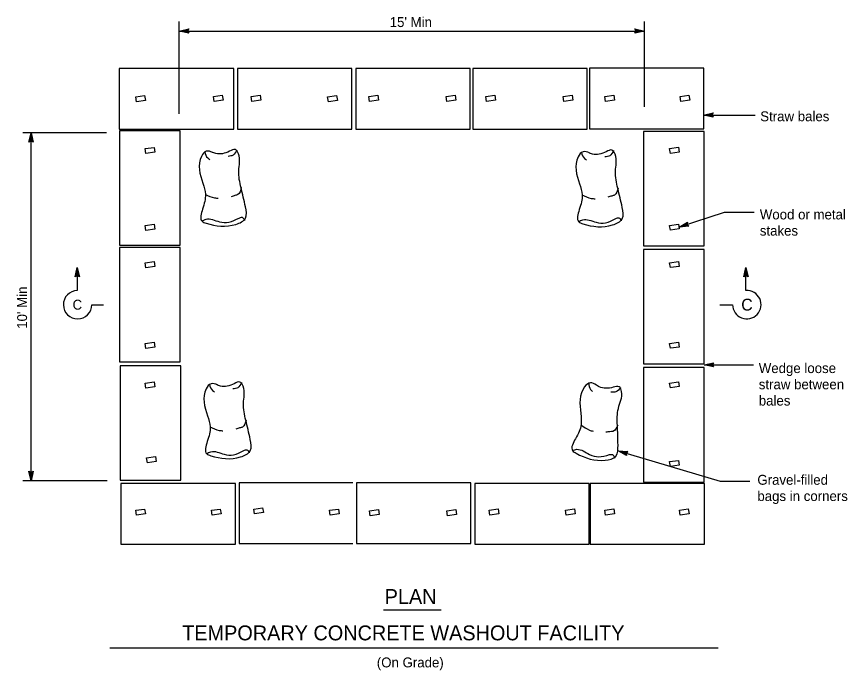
# Model space of a CAD drawing. Extents: x 6708826 to 6711089, y 1868571 to 1869537.
# Drawn here: x 6709434 to 6709938, y 1868641 to 1869038 of the extents above; entities that cross this region are included whole.
import ezdxf

# ---------------------------------------------------------------- set-up
doc = ezdxf.new("R2010")
doc.units = 0
for name, color, linetype in [('1 Control', 7, 'Continuous'), ('56 Stg 3 Anno', 7, 'Continuous'), ('57 Undefined', 7, 'Continuous'), ('60 Nongeo Data', 7, 'Continuous')]:
    doc.layers.add(name, color=color, linetype=linetype)

msp = doc.modelspace()

# ---------------------------------------------------------------- linework, layer by layer
at = {"layer": '1 Control'}
for p, q in [((6709798.85, 1868774.43), (6709798.85, 1868774.43)), ((6709804, 1868771.55), (6709804, 1868771.55)), ((6709804.73, 1868774.01), (6709804.73, 1868774.01))]:
    msp.add_line(p, q, dxfattribs=at)
msp.add_lwpolyline([(6709804, 1868771.55), (6709798.85, 1868774.43), (6709804.73, 1868774.01), (6709804.44, 1868773.74), (6709800.13, 1868774.05), (6709803.9, 1868771.94), (6709803.81, 1868772.32), (6709801.39, 1868773.67), (6709804.15, 1868773.48), (6709803.85, 1868773.21), (6709802.66, 1868773.29), (6709803.71, 1868772.71), (6709803.63, 1868773.01), (6709804.73, 1868774.01), (6709803.63, 1868773.01)], close=True, dxfattribs=at)
at = {"layer": '56 Stg 3 Anno'}
for p, q in [((6709532.76, 1868978.54), (6709532.76, 1869034.49)), ((6709814.79, 1868982.86), (6709814.79, 1869034.49)), ((6709532.76, 1869028.82), (6709538.52, 1869030.09)), ((6709532.76, 1869028.82), (6709538.52, 1869030.09)), ((6709532.76, 1869028.82), (6709814.79, 1869028.82)), ((6709538.52, 1869027.53), (6709532.76, 1869028.82)), ((6709532.76, 1869028.82), (6709532.76, 1869028.82)), ((6709538.52, 1869027.53), (6709532.76, 1869028.82)), ((6709532.76, 1869028.82), (6709532.76, 1869028.82)), ((6709538.32, 1869027.87), (6709534.09, 1869028.81)), ((6709538.32, 1869027.87), (6709534.09, 1869028.81)), ((6709534.1, 1869028.82), (6709538.3, 1869029.75)), ((6709534.1, 1869028.82), (6709538.3, 1869029.75)), ((6709535.42, 1869028.81), (6709538.13, 1869029.41)), ((6709535.42, 1869028.81), (6709538.13, 1869029.41)), ((6709538.09, 1869028.22), (6709535.42, 1869028.81)), ((6709538.09, 1869028.22), (6709535.42, 1869028.81)), ((6709536.74, 1869028.81), (6709537.9, 1869029.07)), ((6709536.74, 1869028.81), (6709537.9, 1869029.07)), ((6709537.92, 1869028.55), (6709536.74, 1869028.81)), ((6709537.92, 1869028.55), (6709536.74, 1869028.81)), ((6709538.52, 1869030.09), (6709537.76, 1869028.82)), ((6709538.52, 1869030.09), (6709537.76, 1869028.82)), ((6709537.76, 1869028.82), (6709538.52, 1869027.53)), ((6709537.76, 1869028.82), (6709538.52, 1869027.53)), ((6709538.52, 1869030.09), (6709538.52, 1869030.09)), ((6709538.52, 1869030.09), (6709538.52, 1869030.09)), ((6709538.52, 1869027.53), (6709538.52, 1869027.53)), ((6709538.52, 1869027.53), (6709538.52, 1869027.53)), ((6709809.8, 1869028.82), (6709809.03, 1869030.1)), ((6709809.03, 1869030.1), (6709809.03, 1869030.1)), ((6709809.03, 1869030.1), (6709814.79, 1869028.82)), ((6709814.79, 1869028.82), (6709809.03, 1869027.54)), ((6709809.03, 1869027.54), (6709809.8, 1869028.82)), ((6709809.03, 1869027.54), (6709809.03, 1869027.54)), ((6709809.24, 1869029.76), (6709813.47, 1869028.82)), ((6709813.46, 1869028.81), (6709809.26, 1869027.88)), ((6709812.14, 1869028.82), (6709809.43, 1869028.22)), ((6709809.47, 1869029.41), (6709812.14, 1869028.82)), ((6709809.64, 1869029.08), (6709810.82, 1869028.82)), ((6709810.82, 1869028.82), (6709809.66, 1869028.56)), ((6709814.79, 1869028.82), (6709814.79, 1869028.82)), ((6709850.7, 1868977.91), (6709856.46, 1868979.18)), ((6709850.7, 1868977.91), (6709881.9, 1868977.91)), ((6709856.46, 1868976.62), (6709850.7, 1868977.91)), ((6709850.7, 1868977.91), (6709850.7, 1868977.91)), ((6709856.25, 1868976.96), (6709852.03, 1868977.91)), ((6709852.04, 1868977.91), (6709856.24, 1868978.84)), ((6709853.35, 1868977.91), (6709856.07, 1868978.51)), ((6709856.03, 1868977.31), (6709853.35, 1868977.91)), ((6709854.68, 1868977.9), (6709855.84, 1868978.16)), ((6709855.86, 1868977.64), (6709854.68, 1868977.9)), ((6709856.46, 1868979.18), (6709855.69, 1868977.91)), ((6709855.69, 1868977.91), (6709856.46, 1868976.62)), ((6709856.46, 1868979.18), (6709856.46, 1868979.18)), ((6709856.46, 1868976.62), (6709856.46, 1868976.62)), ((6709488.73, 1868967.19), (6709437.9, 1868967.19)), ((6709441.64, 1868961.43), (6709442.93, 1868967.19)), ((6709442.93, 1868756.37), (6709442.93, 1868967.19)), ((6709442.93, 1868967.19), (6709442.93, 1868967.19)), ((6709442.93, 1868967.19), (6709444.2, 1868961.43)), ((6709442.93, 1868962.19), (6709441.64, 1868961.43)), ((6709441.64, 1868961.43), (6709441.64, 1868961.43)), ((6709441.98, 1868961.63), (6709442.93, 1868965.86)), ((6709442.33, 1868961.86), (6709442.93, 1868964.53)), ((6709442.66, 1868962.03), (6709442.92, 1868963.21)), ((6709442.92, 1868963.21), (6709443.18, 1868962.05)), ((6709442.93, 1868965.85), (6709443.86, 1868961.65)), ((6709442.93, 1868964.53), (6709443.53, 1868961.82)), ((6709444.2, 1868961.43), (6709442.93, 1868962.19)), ((6709444.2, 1868961.43), (6709444.2, 1868961.43)), ((6709863.16, 1868918.83), (6709835.83, 1868909.95)), ((6709881.39, 1868918.83), (6709863.16, 1868918.83)), ((6709835.83, 1868909.95), (6709840.91, 1868912.94)), ((6709837.1, 1868910.36), (6709840.8, 1868912.54)), ((6709838.35, 1868910.76), (6709840.74, 1868912.17)), ((6709841.08, 1868911.02), (6709838.35, 1868910.76)), ((6709839.61, 1868911.17), (6709840.64, 1868911.78)), ((6709840.82, 1868911.29), (6709839.61, 1868911.17)), ((6709840.91, 1868912.94), (6709840.58, 1868911.49)), ((6709840.58, 1868911.49), (6709841.7, 1868910.5)), ((6709840.91, 1868912.94), (6709840.91, 1868912.94)), ((6709841.7, 1868910.5), (6709835.83, 1868909.95)), ((6709835.83, 1868909.95), (6709835.83, 1868909.95)), ((6709841.4, 1868910.76), (6709837.09, 1868910.36)), ((6709841.7, 1868910.5), (6709841.7, 1868910.5)), ((6709469.7, 1868879.8), (6709470.99, 1868885.56)), ((6709470.05, 1868880.01), (6709470.99, 1868884.24)), ((6709470.39, 1868880.23), (6709470.99, 1868882.91)), ((6709470.73, 1868880.4), (6709470.99, 1868881.58)), ((6709470.99, 1868885.56), (6709470.99, 1868885.56)), ((6709470.99, 1868885.56), (6709472.27, 1868879.8)), ((6709470.99, 1868885.56), (6709470.99, 1868871.63)), ((6709470.99, 1868884.23), (6709471.92, 1868880.02)), ((6709470.99, 1868882.91), (6709471.59, 1868880.19)), ((6709470.99, 1868881.58), (6709471.25, 1868880.42)), ((6709875.11, 1868879.8), (6709876.4, 1868885.56)), ((6709875.45, 1868880), (6709876.4, 1868884.23)), ((6709875.8, 1868880.23), (6709876.4, 1868882.91)), ((6709876.13, 1868880.4), (6709876.4, 1868881.58)), ((6709876.4, 1868885.56), (6709876.4, 1868885.56)), ((6709876.4, 1868885.56), (6709877.68, 1868879.8)), ((6709876.4, 1868871.63), (6709876.4, 1868885.56)), ((6709876.4, 1868884.22), (6709877.33, 1868880.02)), ((6709876.4, 1868882.91), (6709877, 1868880.19)), ((6709876.4, 1868881.58), (6709876.65, 1868880.42)), ((6709470.99, 1868880.57), (6709469.7, 1868879.8)), ((6709469.7, 1868879.8), (6709469.7, 1868879.8)), ((6709472.27, 1868879.8), (6709470.99, 1868880.57)), ((6709472.27, 1868879.8), (6709472.27, 1868879.8)), ((6709876.4, 1868880.56), (6709875.11, 1868879.8)), ((6709875.11, 1868879.8), (6709875.11, 1868879.8)), ((6709877.68, 1868879.8), (6709876.4, 1868880.56)), ((6709877.68, 1868879.8), (6709877.68, 1868879.8)), ((6709479.79, 1868863), (6709486.92, 1868863)), ((6709860.6, 1868863), (6709868.33, 1868863)), ((6709851, 1868826.55), (6709856.76, 1868827.82)), ((6709851, 1868826.55), (6709880.87, 1868826.55)), ((6709856.76, 1868825.26), (6709851, 1868826.55)), ((6709851, 1868826.55), (6709851, 1868826.55)), ((6709856.55, 1868825.6), (6709852.33, 1868826.55)), ((6709852.34, 1868826.55), (6709856.54, 1868827.48)), ((6709853.65, 1868826.54), (6709856.37, 1868827.15)), ((6709856.33, 1868825.95), (6709853.65, 1868826.54)), ((6709854.98, 1868826.54), (6709856.14, 1868826.8)), ((6709856.16, 1868826.28), (6709854.98, 1868826.54)), ((6709856.76, 1868827.82), (6709855.99, 1868826.55)), ((6709855.99, 1868826.55), (6709856.76, 1868825.26)), ((6709856.76, 1868827.82), (6709856.76, 1868827.82)), ((6709856.76, 1868825.26), (6709856.76, 1868825.26)), ((6709798.85, 1868774.43), (6709860.68, 1868756.04)), ((6709442.93, 1868756.37), (6709441.65, 1868762.14)), ((6709441.65, 1868762.14), (6709441.65, 1868762.14)), ((6709441.65, 1868762.14), (6709442.93, 1868761.37)), ((6709442.92, 1868757.71), (6709442, 1868761.91)), ((6709442.93, 1868759.03), (6709442.33, 1868761.74)), ((6709442.93, 1868760.35), (6709442.67, 1868761.51)), ((6709442.93, 1868761.37), (6709444.21, 1868762.14)), ((6709444.21, 1868762.14), (6709442.93, 1868756.37)), ((6709443.87, 1868761.93), (6709442.93, 1868757.7)), ((6709443.53, 1868761.7), (6709442.93, 1868759.03)), ((6709443.19, 1868761.53), (6709442.93, 1868760.35)), ((6709444.21, 1868762.14), (6709444.21, 1868762.14)), ((6709489.1, 1868756.37), (6709437.9, 1868756.37)), ((6709442.93, 1868756.37), (6709442.93, 1868756.37)), ((6709860.68, 1868756.04), (6709878.82, 1868756.04))]:
    msp.add_line(p, q, dxfattribs=at)
for centre, start, end in [((6709471.16, 1868863.01), 91.113, 359.9585), ((6709876.92, 1868863.01), 180.1055, 93.4975)]:
    msp.add_arc(centre, 8.62, start, end, dxfattribs=at)
at = {"layer": '57 Undefined'}
for p, q in [((6709656.61, 1868678.17), (6709691.63, 1868678.17)), ((6709490.67, 1868655.17), (6709859.6, 1868655.17))]:
    msp.add_line(p, q, dxfattribs=at)
at = {"layer": '60 Nongeo Data'}
for points in [[(6709496.47, 1868969.31), (6709565.82, 1868969.31), (6709565.82, 1869006.05), (6709496.47, 1869006.05)], [(6709568.1, 1868969.31), (6709637.45, 1868969.31), (6709637.45, 1869006.05), (6709568.1, 1869006.05)], [(6709639.88, 1868969.38), (6709709.24, 1868969.38), (6709709.24, 1869006.12), (6709639.88, 1869006.12)], [(6709710.76, 1868969.38), (6709780.11, 1868969.38), (6709780.11, 1869006.12), (6709710.76, 1869006.12)], [(6709781.56, 1868969.48), (6709850.91, 1868969.48), (6709850.91, 1869006.23), (6709781.56, 1869006.23)], [(6709506.39, 1868989.01), (6709511.83, 1868989.8), (6709512.26, 1868986.8), (6709506.83, 1868986.01)], [(6709553.5, 1868989.11), (6709558.93, 1868989.9), (6709559.37, 1868986.9), (6709553.94, 1868986.11)], [(6709576.44, 1868989.11), (6709581.87, 1868989.9), (6709582.31, 1868986.9), (6709576.87, 1868986.11)], [(6709622.79, 1868989.01), (6709628.22, 1868989.8), (6709628.66, 1868986.8), (6709623.23, 1868986.01)], [(6709647.74, 1868989.18), (6709653.17, 1868989.97), (6709653.6, 1868986.97), (6709648.17, 1868986.18)], [(6709694.65, 1868989.08), (6709700.08, 1868989.87), (6709700.51, 1868986.87), (6709695.08, 1868986.08)], [(6709718.61, 1868989.18), (6709724.04, 1868989.97), (6709724.48, 1868986.97), (6709719.05, 1868986.18)], [(6709765.52, 1868989.08), (6709770.95, 1868989.87), (6709771.39, 1868986.87), (6709765.95, 1868986.08)], [(6709790.84, 1868989.18), (6709796.27, 1868989.97), (6709796.71, 1868986.97), (6709791.27, 1868986.18)], [(6709836.41, 1868989.18), (6709841.84, 1868989.97), (6709842.27, 1868986.97), (6709836.84, 1868986.18)], [(6709533.27, 1868899), (6709533.27, 1868968.35), (6709496.52, 1868968.35), (6709496.52, 1868899)], [(6709851, 1868898.66), (6709851, 1868968.01), (6709814.26, 1868968.01), (6709814.26, 1868898.66)], [(6709512.19, 1868957.54), (6709517.62, 1868958.33), (6709518.06, 1868955.33), (6709512.63, 1868954.54)], [(6709830.11, 1868957.61), (6709835.55, 1868958.4), (6709835.98, 1868955.4), (6709830.55, 1868954.61)], [(6709512.19, 1868911.01), (6709517.62, 1868911.8), (6709518.06, 1868908.81), (6709512.63, 1868908.01)], [(6709830.11, 1868911.08), (6709835.55, 1868911.87), (6709835.98, 1868908.88), (6709830.55, 1868908.08)], [(6709533.27, 1868828.33), (6709533.27, 1868897.68), (6709496.52, 1868897.68), (6709496.52, 1868828.33)], [(6709851, 1868827.19), (6709851, 1868896.54), (6709814.26, 1868896.54), (6709814.26, 1868827.19)], [(6709512.19, 1868888.37), (6709517.62, 1868889.16), (6709518.06, 1868886.16), (6709512.63, 1868885.37)], [(6709830.11, 1868888.44), (6709835.55, 1868889.23), (6709835.98, 1868886.23), (6709830.55, 1868885.44)], [(6709830.11, 1868839.56), (6709835.55, 1868840.36), (6709835.98, 1868837.36), (6709830.55, 1868836.57)], [(6709512.19, 1868839.49), (6709517.62, 1868840.29), (6709518.06, 1868837.29), (6709512.63, 1868836.49)], [(6709533.67, 1868756.69), (6709533.67, 1868826.04), (6709496.93, 1868826.04), (6709496.93, 1868756.69)], [(6709851, 1868755.55), (6709851, 1868824.91), (6709814.26, 1868824.91), (6709814.26, 1868755.55)], [(6709512.19, 1868815.48), (6709517.62, 1868816.27), (6709518.06, 1868813.27), (6709512.63, 1868812.48)], [(6709830.11, 1868815.55), (6709835.55, 1868816.34), (6709835.98, 1868813.34), (6709830.55, 1868812.55)], [(6709513.04, 1868770.2), (6709518.47, 1868770.99), (6709518.9, 1868767.99), (6709513.47, 1868767.2)], [(6709830.11, 1868767.91), (6709835.55, 1868768.7), (6709835.98, 1868765.7), (6709830.55, 1868764.91)], [(6709640.26, 1868718.35), (6709709.61, 1868718.35), (6709709.61, 1868755.09), (6709640.26, 1868755.09)], [(6709711.97, 1868717.97), (6709781.32, 1868717.97), (6709781.32, 1868754.71), (6709711.97, 1868754.71)], [(6709781.97, 1868717.97), (6709851.32, 1868717.97), (6709851.32, 1868754.72), (6709781.97, 1868754.72)], [(6709497.47, 1868717.9), (6709566.82, 1868717.9), (6709566.82, 1868754.64), (6709497.47, 1868754.64)], [(6709577.94, 1868739.21), (6709583.37, 1868740), (6709583.81, 1868737), (6709578.37, 1868736.21)], [(6709506.39, 1868738.43), (6709511.83, 1868739.22), (6709512.26, 1868736.22), (6709506.83, 1868735.43)], [(6709552.27, 1868738.43), (6709557.7, 1868739.22), (6709558.14, 1868736.22), (6709552.71, 1868735.43)], [(6709623.88, 1868738.43), (6709629.31, 1868739.22), (6709629.75, 1868736.22), (6709624.32, 1868735.43)], [(6709648.11, 1868738.15), (6709653.54, 1868738.94), (6709653.98, 1868735.94), (6709648.55, 1868735.15)], [(6709695.02, 1868738.05), (6709700.45, 1868738.84), (6709700.89, 1868735.84), (6709695.46, 1868735.05)], [(6709720.66, 1868738.5), (6709726.09, 1868739.29), (6709726.53, 1868736.29), (6709721.1, 1868735.5)], [(6709766.98, 1868738.5), (6709772.41, 1868739.29), (6709772.85, 1868736.29), (6709767.42, 1868735.5)], [(6709790.85, 1868738.5), (6709796.28, 1868739.29), (6709796.72, 1868736.29), (6709791.29, 1868735.5)], [(6709836.02, 1868738.5), (6709841.45, 1868739.29), (6709841.88, 1868736.29), (6709836.45, 1868735.5)]]:
    msp.add_lwpolyline(points, close=True, dxfattribs=at)
msp.add_lwpolyline([(6709638.13, 1868755.02), (6709569.11, 1868755.02), (6709569.11, 1868718.28), (6709638.13, 1868718.28)], dxfattribs=at)
for points in [[(6709553.06, 1868955.3), (6709549.22, 1868956.01), (6709546.23, 1868952.89), (6709547.09, 1868936.55), (6709548.65, 1868929.87), (6709546.94, 1868920.92), (6709546.66, 1868913.53), (6709549.08, 1868912.4), (6709567.16, 1868911.69), (6709572.99, 1868915.38), (6709572.99, 1868922.2), (6709570.29, 1868933.85), (6709568.86, 1868944.08), (6709568.72, 1868954.45), (6709566.73, 1868957.01), (6709563.31, 1868956.01), (6709554.91, 1868954.59), (6709552.64, 1868955.44)], [(6709567.73, 1868956.72), (6709565.45, 1868953.6), (6709562.46, 1868952.89)], [(6709781.46, 1868954.97), (6709777.61, 1868955.68), (6709774.62, 1868952.56), (6709775.48, 1868936.22), (6709777.04, 1868929.54), (6709775.33, 1868920.59), (6709775.05, 1868913.21), (6709777.47, 1868912.07), (6709795.55, 1868911.36), (6709801.38, 1868915.05), (6709801.38, 1868921.87), (6709798.68, 1868933.52), (6709797.26, 1868943.75), (6709797.11, 1868954.12), (6709795.12, 1868956.68), (6709791.7, 1868955.68), (6709783.31, 1868954.26), (6709781.03, 1868955.12)], [(6709796.12, 1868956.39), (6709793.84, 1868953.27), (6709790.85, 1868952.56)], [(6709548.22, 1868955.58), (6709550.07, 1868951.89), (6709551.36, 1868951.04)], [(6709776.62, 1868955.26), (6709778.47, 1868951.56), (6709779.75, 1868950.71)], [(6709570.43, 1868933.99), (6709568.3, 1868929.73), (6709566.59, 1868929.16), (6709564.31, 1868928.45)], [(6709798.82, 1868933.66), (6709796.69, 1868929.4), (6709794.98, 1868928.83), (6709792.7, 1868928.12)], [(6709548.51, 1868929.87), (6709554.2, 1868927.74), (6709556.48, 1868927.46)], [(6709776.9, 1868929.54), (6709782.59, 1868927.41), (6709784.87, 1868927.13)], [(6709546.52, 1868913.53), (6709549.08, 1868914.81), (6709557.19, 1868913.25), (6709562.89, 1868912.97), (6709569.15, 1868915.52), (6709570.86, 1868915.95), (6709572.42, 1868914.1)], [(6709774.91, 1868913.21), (6709777.47, 1868914.48), (6709785.58, 1868912.92), (6709791.28, 1868912.64), (6709797.54, 1868915.19), (6709799.25, 1868915.62), (6709800.81, 1868913.77)], [(6709555.91, 1868814.44), (6709552.07, 1868815.15), (6709549.08, 1868812.02), (6709549.93, 1868795.69), (6709551.5, 1868789.01), (6709549.79, 1868780.06), (6709549.51, 1868772.67), (6709551.93, 1868771.53), (6709570, 1868770.82), (6709575.84, 1868774.52), (6709575.84, 1868781.34), (6709573.14, 1868792.99), (6709571.71, 1868803.21), (6709571.57, 1868813.59), (6709569.58, 1868816.14), (6709566.16, 1868815.15), (6709557.76, 1868813.73), (6709555.48, 1868814.58)], [(6709570.57, 1868815.86), (6709568.3, 1868812.73), (6709565.31, 1868812.02)], [(6709785.77, 1868814.31), (6709782.14, 1868815.76), (6709778.6, 1868813.28), (6709776.23, 1868797.09), (6709776.46, 1868790.24), (6709773.03, 1868781.8), (6709771.3, 1868774.61), (6709773.45, 1868773.02), (6709791.03, 1868768.78), (6709797.48, 1868771.25), (6709798.82, 1868777.94), (6709798.45, 1868789.89), (6709799.06, 1868800.2), (6709800.96, 1868810.4), (6709799.51, 1868813.3), (6709795.96, 1868812.99), (6709787.45, 1868813.25), (6709785.38, 1868814.53)], [(6709781.08, 1868815.54), (6709782.17, 1868811.55), (6709783.26, 1868810.47)], [(6709551.07, 1868814.72), (6709552.92, 1868811.03), (6709554.2, 1868810.18)], [(6709800.43, 1868812.83), (6709797.58, 1868810.21), (6709794.51, 1868810.1)], [(6709573.28, 1868793.13), (6709571.14, 1868788.87), (6709569.43, 1868788.3), (6709567.16, 1868787.59)], [(6709776.32, 1868790.27), (6709781.48, 1868787.06), (6709783.66, 1868786.34)], [(6709798.62, 1868790.01), (6709795.69, 1868786.25), (6709793.9, 1868786.02), (6709791.53, 1868785.77)], [(6709551.36, 1868789.01), (6709557.05, 1868786.88), (6709559.33, 1868786.59)], [(6709549.36, 1868772.67), (6709551.93, 1868773.95), (6709560.04, 1868772.39), (6709565.73, 1868772.1), (6709572, 1868774.66), (6709573.7, 1868775.09), (6709575.27, 1868773.24)], [(6709771.16, 1868774.64), (6709773.92, 1868775.39), (6709781.57, 1868772.27), (6709787.1, 1868770.87), (6709793.74, 1868772.15), (6709795.5, 1868772.23), (6709796.67, 1868770.11)]]:
    msp.add_spline(points, degree=3, dxfattribs=at)

# ---------------------------------------------------------------- texts
at = {"layer": '57 Undefined'}
for s, height, p in [("15' Min", 6, (6709660.4, 1869031.22)), ('Straw bales', 6, (6709885.05, 1868974.14)), ('Wood or metal', 6, (6709884.8, 1868914.68)), ('stakes', 6, (6709884.8, 1868904.84)), ('C', 6, (6709468.13, 1868860.01)), ('C', 7.21, (6709873.53, 1868859.41)), ('Wedge loose', 6, (6709884.17, 1868821.58)), ('straw between', 6, (6709884.17, 1868811.74)), ('bales', 6, (6709884.17, 1868801.9)), ('Gravel-filled', 6, (6709883.32, 1868753.9)), ('bags in corners', 6, (6709883.32, 1868744.06)), ('PLAN', 9, (6709657.35, 1868681.69)), ('TEMPORARY CONCRETE WASHOUT FACILITY', 9, (6709534.6, 1868659.65)), ('(On Grade)', 6, (6709652.59, 1868643.26))]:
    msp.add_text(s, height=height, dxfattribs=at).set_placement(p)
msp.add_text("10' Min", height=6, rotation=90, dxfattribs=at).set_placement((6709440.53, 1868848.4))

doc.saveas('drawing.dxf')
